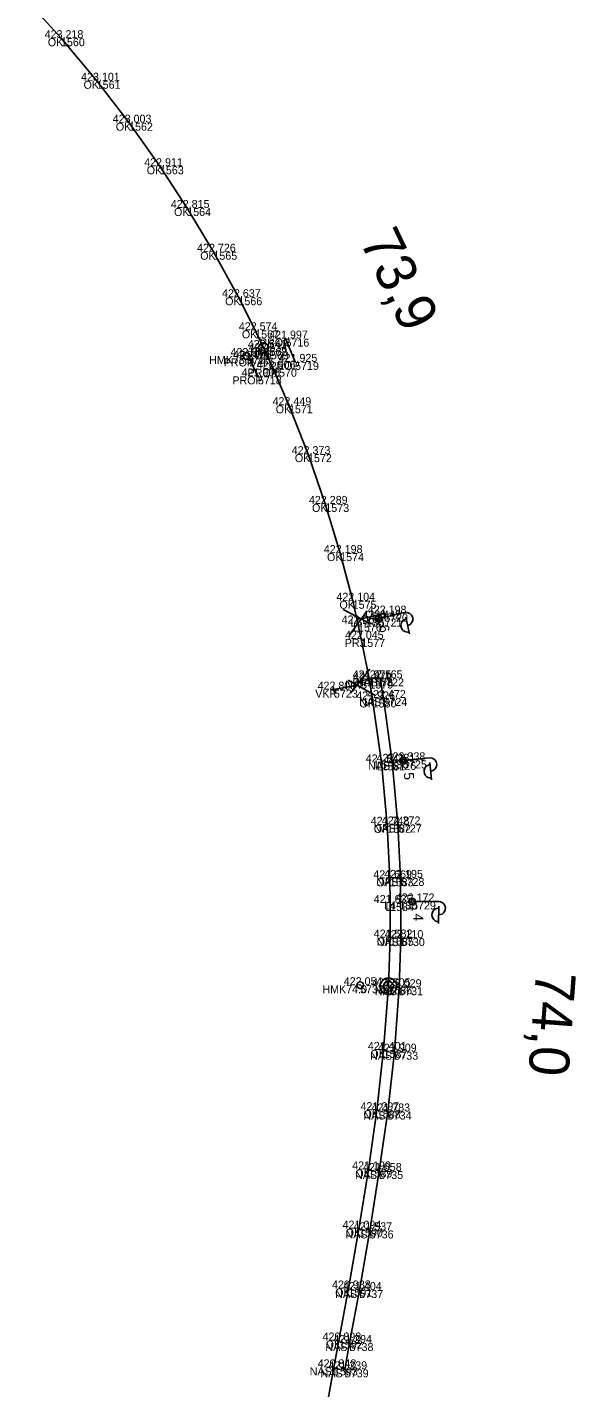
# Model space of a CAD drawing. Extents: x -621782 to -610392, y -1141853 to -1122321.
# Drawn here: x -619487.9 to -619405.6, y -1129772.6 to -1129568.6 of the extents above; entities that cross this region are included whole.
import ezdxf

# ---------------------------------------------------------------- set-up
doc = ezdxf.new("R2010")
doc.units = 0
for name, color, linetype in [('Vrstva 1', 7, 'Continuous'), ('Vrstva 14', 7, 'Continuous'), ('Vrstva 19', 7, 'Continuous'), ('Vrstva 25', 7, 'Continuous'), ('Vrstva 4', 7, 'Continuous'), ('Vrstva 60', 7, 'Continuous'), ('Vrstva 61', 7, 'Continuous'), ('Vrstva 62', 7, 'Continuous'), ('Vrstva 7', 7, 'Continuous')]:
    doc.layers.add(name, color=color, linetype=linetype)

msp = doc.modelspace()

# ---------------------------------------------------------------- linework, layer by layer
at = {"layer": 'Vrstva 1'}
msp.add_lwpolyline([(-619487.87, -1129564.71), (-619482.8, -1129570.29), (-619477.44, -1129576.67), (-619472.59, -1129582.96), (-619467.96, -1129589.49), (-619463.87, -1129595.75), (-619459.94, -1129602.31), (-619456.19, -1129609.13), (-619453.68, -1129614.09), (-619452.42, -1129616.74), (-619452.2, -1129617.22), (-619450.99, -1129619.85), (-619448.62, -1129625.32), (-619445.75, -1129632.66), (-619443.16, -1129640.12), (-619440.93, -1129647.49), (-619439.05, -1129654.64), (-619438.26, -1129658.05), (-619437.76, -1129660.36), (-619436.6, -1129666.28), (-619436.54, -1129666.6), (-619436.06, -1129669.44), (-619434.74, -1129678.88), (-619433.89, -1129688.23), (-619433.5, -1129696.26), (-619433.44, -1129699.96), (-619433.45, -1129705.14), (-619433.7, -1129712.45), (-619434.42, -1129721.99), (-619435.43, -1129731.03), (-619436.68, -1129739.9), (-619438.11, -1129748.79), (-619439.69, -1129757.76), (-619441.12, -1129765.56), (-619441.86, -1129769.59), (-619442.93, -1129775.41)], dxfattribs=at)
at = {"layer": 'Vrstva 14'}
msp.add_lwpolyline([(-619440.23, -1129769.88), (-619439.51, -1129765.93), (-619438.05, -1129757.99), (-619436.49, -1129749.04), (-619435.06, -1129740.14), (-619433.8, -1129731.22), (-619432.8, -1129722.25), (-619432.08, -1129712.58), (-619431.81, -1129705.22), (-619431.87, -1129696.19), (-619432.26, -1129688.18), (-619433.11, -1129678.79), (-619434.44, -1129669.22), (-619434.93, -1129666.27)], dxfattribs=at)
at = {"layer": 'Vrstva 19'}
for p, q in [((-619449.13, -1129615.33), (-619447.7, -1129618.82)), ((-619454.55, -1129618.31), (-619453.27, -1129620.99))]:
    msp.add_line(p, q, dxfattribs=at)
at = {"layer": 'Vrstva 25'}
for p, q in [((-619434.67, -1129657.2), (-619431.26, -1129656.41)), ((-619435.64, -1129657.18), (-619434.82, -1129657.69)), ((-619435.41, -1129656.88), (-619434.66, -1129657.35)), ((-619431.1, -1129657.09), (-619430.51, -1129659.62)), ((-619431.96, -1129678.38), (-619431.22, -1129678.99)), ((-619431.69, -1129678.11), (-619431.02, -1129678.68)), ((-619431.01, -1129678.53), (-619427.52, -1129678.21)), ((-619427.46, -1129678.91), (-619427.22, -1129681.5)), ((-619430.59, -1129699.49), (-619429.91, -1129700.17)), ((-619430.3, -1129699.25), (-619429.68, -1129699.88)), ((-619429.65, -1129699.73), (-619426.15, -1129699.74)), ((-619426.15, -1129700.44), (-619426.16, -1129703.04))]:
    msp.add_line(p, q, dxfattribs=at)
for centre in [(-619435.16, -1129657.31), (-619431.5, -1129678.57), (-619430.15, -1129699.73)]:
    msp.add_circle(centre, 0.5, dxfattribs=at)
for centre, start, end in [((-619431.03, -1129657.38), 283.0782, 103.0782), ((-619430.82, -1129658.36), 102.3756, 283.7807), ((-619427.43, -1129679.21), 275.1856, 95.1856), ((-619427.35, -1129680.21), 94.483, 275.8882), ((-619426.17, -1129701.74), 89.1427, 270.5478), ((-619426.15, -1129700.74), 269.8452, 89.8452)]:
    msp.add_arc(centre, 1, start, end, dxfattribs=at)
at = {"layer": 'Vrstva 4'}
for p, q in [((-619436.4, -1129658.08), (-619440.49, -1129655.95)), ((-619439.59, -1129659.84), (-619436.86, -1129656.13)), ((-619434.34, -1129656.57), (-619437.77, -1129657.37)), ((-619434.23, -1129657.06), (-619434.45, -1129656.08)), ((-619437.76, -1129660.36), (-619436.6, -1129666.28)), ((-619439.75, -1129666.54), (-619435.74, -1129668.81)), ((-619436.5, -1129664.89), (-619439.37, -1129668.5)), ((-619441.96, -1129667.48), (-619441.77, -1129668.46)), ((-619441.86, -1129667.97), (-619438.41, -1129667.3))]:
    msp.add_line(p, q, dxfattribs=at)
at = {"layer": 'Vrstva 60'}
for p, q in [((-619482.8, -1129570.29), (-619482.8, -1129570.29)), ((-619477.44, -1129576.67), (-619477.44, -1129576.67)), ((-619472.59, -1129582.96), (-619472.59, -1129582.96)), ((-619467.96, -1129589.49), (-619467.96, -1129589.49)), ((-619463.87, -1129595.75), (-619463.87, -1129595.75)), ((-619459.94, -1129602.31), (-619459.94, -1129602.31)), ((-619456.19, -1129609.13), (-619456.19, -1129609.13)), ((-619453.68, -1129614.09), (-619453.68, -1129614.09)), ((-619449.13, -1129615.33), (-619449.13, -1129615.33)), ((-619452.42, -1129616.74), (-619452.42, -1129616.74)), ((-619452.2, -1129617.22), (-619452.2, -1129617.22)), ((-619454.93, -1129617.95), (-619454.93, -1129617.95)), ((-619454.55, -1129618.31), (-619454.55, -1129618.31)), ((-619450.99, -1129619.85), (-619450.99, -1129619.85)), ((-619447.7, -1129618.82), (-619447.7, -1129618.82)), ((-619453.27, -1129620.99), (-619453.27, -1129620.99)), ((-619448.62, -1129625.32), (-619448.62, -1129625.32)), ((-619445.75, -1129632.66), (-619445.75, -1129632.66)), ((-619443.16, -1129640.12), (-619443.16, -1129640.12)), ((-619440.93, -1129647.49), (-619440.93, -1129647.49)), ((-619439.05, -1129654.64), (-619439.05, -1129654.64)), ((-619434.34, -1129656.57), (-619434.34, -1129656.57)), ((-619438.26, -1129658.05), (-619438.26, -1129658.05)), ((-619435.16, -1129657.31), (-619435.16, -1129657.31)), ((-619437.76, -1129660.36), (-619437.76, -1129660.36)), ((-619436.6, -1129666.28), (-619436.6, -1129666.28)), ((-619436.54, -1129666.6), (-619436.54, -1129666.6)), ((-619434.93, -1129666.27), (-619434.93, -1129666.27)), ((-619441.86, -1129667.97), (-619441.86, -1129667.97)), ((-619436.06, -1129669.44), (-619436.06, -1129669.44)), ((-619434.44, -1129669.22), (-619434.44, -1129669.22)), ((-619434.74, -1129678.88), (-619434.74, -1129678.88)), ((-619433.11, -1129678.79), (-619433.11, -1129678.79)), ((-619431.5, -1129678.57), (-619431.5, -1129678.57)), ((-619433.89, -1129688.23), (-619433.89, -1129688.23)), ((-619432.26, -1129688.18), (-619432.26, -1129688.18)), ((-619433.5, -1129696.26), (-619433.5, -1129696.26)), ((-619431.87, -1129696.19), (-619431.87, -1129696.19)), ((-619433.44, -1129699.96), (-619433.44, -1129699.96)), ((-619430.15, -1129699.73), (-619430.15, -1129699.73)), ((-619433.45, -1129705.14), (-619433.45, -1129705.14)), ((-619431.81, -1129705.22), (-619431.81, -1129705.22)), ((-619437.94, -1129712.29), (-619437.94, -1129712.29)), ((-619433.7, -1129712.45), (-619433.7, -1129712.45)), ((-619432.08, -1129712.58), (-619432.08, -1129712.58)), ((-619434.42, -1129721.99), (-619434.42, -1129721.99)), ((-619432.8, -1129722.25), (-619432.8, -1129722.25)), ((-619435.43, -1129731.03), (-619435.43, -1129731.03)), ((-619433.8, -1129731.22), (-619433.8, -1129731.22)), ((-619436.68, -1129739.9), (-619436.68, -1129739.9)), ((-619435.06, -1129740.14), (-619435.06, -1129740.14)), ((-619438.11, -1129748.79), (-619438.11, -1129748.79)), ((-619436.49, -1129749.04), (-619436.49, -1129749.04)), ((-619439.69, -1129757.76), (-619439.69, -1129757.76)), ((-619438.05, -1129757.99), (-619438.05, -1129757.99)), ((-619441.12, -1129765.56), (-619441.12, -1129765.56)), ((-619439.51, -1129765.93), (-619439.51, -1129765.93)), ((-619441.86, -1129769.59), (-619441.86, -1129769.59)), ((-619440.23, -1129769.88), (-619440.23, -1129769.88))]:
    msp.add_line(p, q, dxfattribs=at)
at = {"layer": 'Vrstva 7'}
for p, q in [((-619454.95, -1129617.91), (-619454.9, -1129618)), ((-619437.94, -1129712.24), (-619437.94, -1129712.34))]:
    msp.add_line(p, q, dxfattribs=at)
for centre, radius in [((-619454.93, -1129617.95), 0.5), ((-619452.42, -1129616.74), 0.75), ((-619433.7, -1129712.45), 1.25), ((-619433.7, -1129712.45), 0.752), ((-619437.94, -1129712.29), 0.5)]:
    msp.add_circle(centre, radius, dxfattribs=at)

# ---------------------------------------------------------------- texts
at = {"layer": 'Vrstva 25'}
for s, rotation, p in [('6', 283.0782, (-619435.16, -1129658.45)), ('5', 275.1856, (-619431.41, -1129680.44)), ('4', 269.8452, (-619429.97, -1129701.53))]:
    msp.add_text(s, height=1.5, rotation=rotation, dxfattribs=at).set_placement(p)
at = {"layer": 'Vrstva 60'}
for s, p in [('1560', (-619482.8, -1129571.49)), ('1561', (-619477.44, -1129577.87)), ('1562', (-619472.59, -1129584.16)), ('1563', (-619467.96, -1129590.69)), ('1564', (-619463.87, -1129596.95)), ('1565', (-619459.94, -1129603.51)), ('1566', (-619456.19, -1129610.33)), ('1567', (-619453.68, -1129615.29)), ('5716', (-619449.13, -1129616.53)), ('1568', (-619452.42, -1129617.94)), ('1569', (-619452.2, -1129618.42)), ('5715', (-619454.93, -1129619.15)), ('5717', (-619454.55, -1129619.51)), ('1570', (-619450.99, -1129621.05)), ('5719', (-619447.7, -1129620.02)), ('5718', (-619453.27, -1129622.19)), ('1571', (-619448.62, -1129626.53)), ('1572', (-619445.75, -1129633.85)), ('1573', (-619443.16, -1129641.32)), ('1574', (-619440.93, -1129648.69)), ('1575', (-619439.05, -1129655.84)), ('5720', (-619434.34, -1129657.77)), ('1576', (-619438.26, -1129659.25)), ('5721', (-619435.16, -1129658.51)), ('1577', (-619437.76, -1129661.56)), ('1578', (-619436.6, -1129667.48)), ('1579', (-619436.54, -1129667.8)), ('5722', (-619434.93, -1129667.47)), ('5723', (-619441.86, -1129669.17)), ('1580', (-619436.06, -1129670.64)), ('5724', (-619434.44, -1129670.42)), ('1581', (-619434.74, -1129680.08)), ('5726', (-619433.11, -1129679.99)), ('5725', (-619431.5, -1129679.78)), ('1582', (-619433.89, -1129689.43)), ('5727', (-619432.26, -1129689.38)), ('1583', (-619433.5, -1129697.46)), ('5728', (-619431.87, -1129697.39)), ('1584', (-619433.44, -1129701.16)), ('5729', (-619430.15, -1129700.93)), ('1585', (-619433.45, -1129706.34)), ('5730', (-619431.81, -1129706.42)), ('5732', (-619437.94, -1129713.49)), ('1586', (-619433.7, -1129713.65)), ('5731', (-619432.08, -1129713.78)), ('1587', (-619434.42, -1129723.19)), ('5733', (-619432.8, -1129723.45)), ('1588', (-619435.43, -1129732.23)), ('5734', (-619433.8, -1129732.42)), ('1589', (-619436.68, -1129741.1)), ('5735', (-619435.06, -1129741.34)), ('1590', (-619438.11, -1129749.99)), ('5736', (-619436.49, -1129750.25)), ('1591', (-619439.69, -1129758.96)), ('5737', (-619438.05, -1129759.19)), ('1592', (-619441.12, -1129766.76)), ('5738', (-619439.51, -1129767.13)), ('1593', (-619441.86, -1129770.79)), ('5739', (-619440.23, -1129771.08))]:
    msp.add_text(s, height=1.2, dxfattribs=at).set_placement(p)
at = {"layer": 'Vrstva 61'}
for s, p in [('423.218', (-619485.25, -1129570.29)), ('423.101', (-619479.79, -1129576.67)), ('423.003', (-619475.04, -1129582.96)), ('422.911', (-619470.32, -1129589.49)), ('422.815', (-619466.33, -1129595.75)), ('422.726', (-619462.39, -1129602.31)), ('422.637', (-619458.65, -1129609.13)), ('422.574', (-619456.13, -1129614.09)), ('422.541', (-619454.78, -1129616.74)), ('421.997', (-619451.58, -1129615.33)), ('422.349', (-619457.38, -1129617.95)), ('421.908', (-619457.01, -1129618.31)), ('422.534', (-619454.65, -1129617.22)), ('421.925', (-619450.16, -1129618.82)), ('421.908', (-619455.72, -1129620.99)), ('422.506', (-619453.44, -1129619.85)), ('422.449', (-619451.07, -1129625.32)), ('422.373', (-619448.2, -1129632.66)), ('422.289', (-619445.62, -1129640.12)), ('422.198', (-619443.38, -1129647.49)), ('422.104', (-619441.5, -1129654.64)), ('422.442', (-619437.6, -1129657.31)), ('422.198', (-619436.79, -1129656.57)), ('422.063', (-619440.71, -1129658.05)), ('422.045', (-619440.21, -1129660.36)), ('422.809', (-619444.32, -1129667.97)), ('421.975', (-619439.06, -1129666.28)), ('421.970', (-619438.99, -1129666.6)), ('422.165', (-619437.38, -1129666.27)), ('421.926', (-619438.51, -1129669.44)), ('422.472', (-619436.89, -1129669.22)), ('421.841', (-619437.1, -1129678.88)), ('422.381', (-619435.47, -1129678.79)), ('422.338', (-619433.96, -1129678.57)), ('421.748', (-619436.35, -1129688.23)), ('422.272', (-619434.7, -1129688.18)), ('421.669', (-619435.96, -1129696.26)), ('422.195', (-619434.32, -1129696.19)), ('421.635', (-619435.89, -1129699.96)), ('422.172', (-619432.6, -1129699.73)), ('421.582', (-619435.9, -1129705.14)), ('422.110', (-619434.26, -1129705.22)), ('422.054', (-619440.39, -1129712.29)), ('421.505', (-619436.16, -1129712.45)), ('422.029', (-619434.53, -1129712.58)), ('421.401', (-619436.78, -1129721.99)), ('421.909', (-619435.26, -1129722.25)), ('421.297', (-619437.88, -1129731.03)), ('421.783', (-619436.25, -1129731.22)), ('421.199', (-619439.13, -1129739.9)), ('421.658', (-619437.51, -1129740.14)), ('421.094', (-619440.57, -1129748.79)), ('421.537', (-619438.94, -1129749.04)), ('420.988', (-619442.15, -1129757.76)), ('421.404', (-619440.5, -1129757.99)), ('420.898', (-619443.57, -1129765.56)), ('421.294', (-619441.96, -1129765.93)), ('420.848', (-619444.31, -1129769.59)), ('421.239', (-619442.69, -1129769.88))]:
    msp.add_text(s, height=1.2, dxfattribs=at).set_placement(p)
at = {"layer": 'Vrstva 62'}
for s, p in [('OK', (-619484.78, -1129571.49)), ('OK', (-619479.42, -1129577.87)), ('OK', (-619474.58, -1129584.16)), ('OK', (-619469.94, -1129590.69)), ('OK', (-619465.85, -1129596.95)), ('OK', (-619461.92, -1129603.51)), ('OK', (-619458.18, -1129610.33)), ('OK', (-619455.67, -1129615.29)), ('PROP', (-619452.97, -1129616.53)), ('HMK73.9', (-619460.59, -1129619.15)), ('PROP', (-619456.03, -1129618.42)), ('HM', (-619454.45, -1129617.94)), ('PROP', (-619458.39, -1129619.51)), ('PROP', (-619454.82, -1129621.05)), ('PROP', (-619451.54, -1129620.02)), ('PROP', (-619457.1, -1129622.19)), ('OK', (-619450.6, -1129626.53)), ('OK', (-619447.73, -1129633.85)), ('OK', (-619445.15, -1129641.32)), ('OK', (-619442.91, -1129648.69)), ('OK', (-619441.04, -1129655.84)), ('VKR', (-619437.15, -1129657.77)), ('L6-130', (-619439.37, -1129658.51)), ('L', (-619438.97, -1129659.25)), ('PRJ', (-619440.24, -1129661.56)), ('NAST', (-619440.18, -1129667.8)), ('PRJ', (-619439.09, -1129667.48)), ('NAST', (-619438.56, -1129667.47)), ('VKR', (-619444.67, -1129669.17)), ('OK', (-619438.04, -1129670.64)), ('NAST', (-619438.08, -1129670.42)), ('NAST', (-619436.75, -1129679.99)), ('L5-130', (-619435.72, -1129679.78)), ('L', (-619435.45, -1129680.08)), ('OK', (-619435.88, -1129689.43)), ('NAST', (-619435.9, -1129689.38)), ('OK', (-619435.49, -1129697.46)), ('NAST', (-619435.51, -1129697.39)), ('L4-130', (-619434.36, -1129700.93)), ('L', (-619434.15, -1129701.16)), ('OK', (-619435.43, -1129706.34)), ('NAST', (-619435.45, -1129706.42)), ('HMK74.0', (-619443.6, -1129713.49)), ('HM', (-619435.74, -1129713.65)), ('NAST', (-619435.72, -1129713.78)), ('OK', (-619436.4, -1129723.19)), ('NAST', (-619436.44, -1129723.45)), ('OK', (-619437.42, -1129732.23)), ('NAST', (-619437.44, -1129732.42)), ('OK', (-619438.66, -1129741.1)), ('NAST', (-619438.7, -1129741.34)), ('OK', (-619440.1, -1129749.99)), ('NAST', (-619440.13, -1129750.25)), ('OK', (-619441.68, -1129758.96)), ('NAST', (-619441.69, -1129759.19)), ('OK', (-619443.1, -1129766.76)), ('NAST', (-619443.15, -1129767.13)), ('NAST', (-619445.5, -1129770.79)), ('NAST', (-619443.87, -1129771.08))]:
    msp.add_text(s, height=1.2, dxfattribs=at).set_placement(p)
at = {"layer": 'Vrstva 7'}
for s, rotation, p in [('73,9', 295.5523, (-619438.08, -1129600.64)), ('74,0', 265.7185, (-619411.54, -1129710.09))]:
    msp.add_text(s, height=6, rotation=rotation, dxfattribs=at).set_placement(p)

doc.saveas('drawing.dxf')
